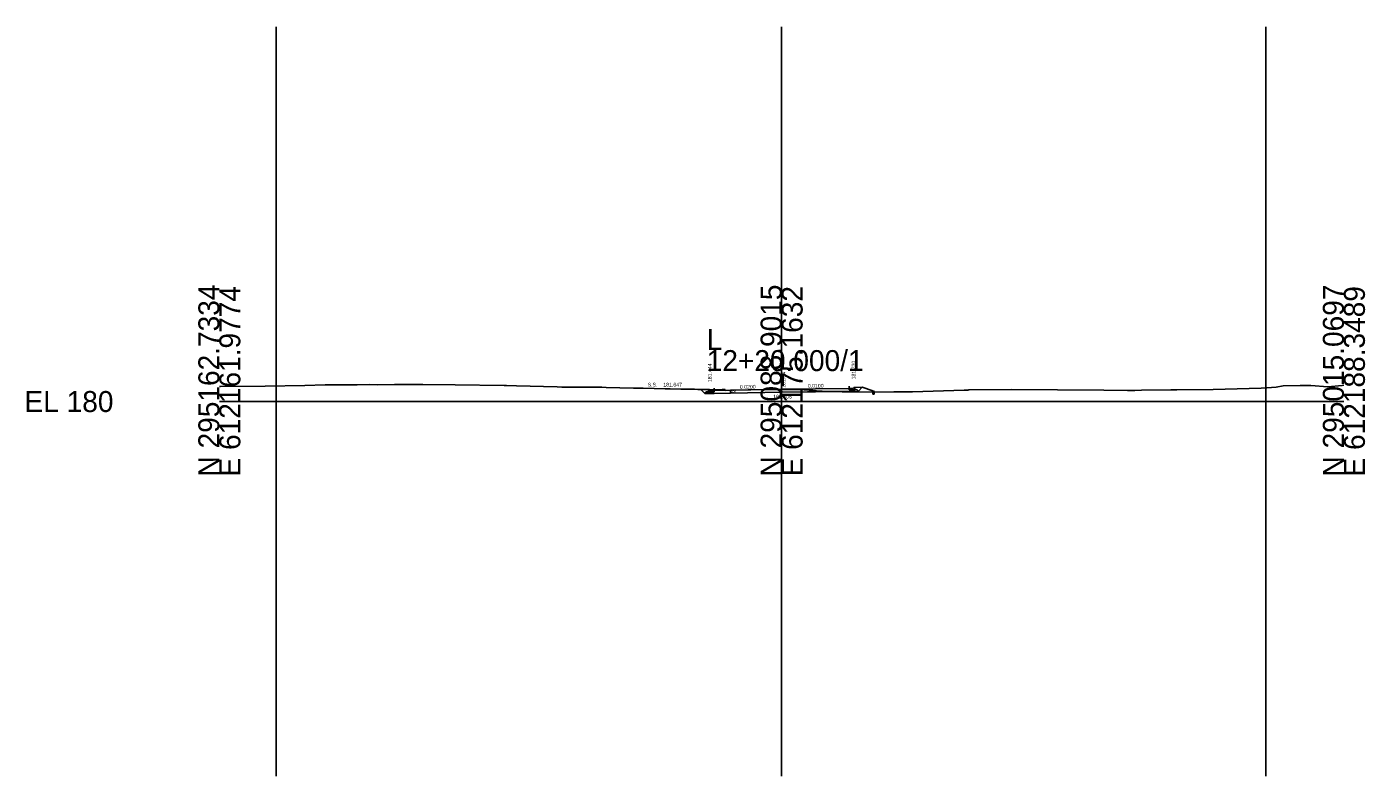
# Model space of a CAD drawing. Extents: x -81 to 616364, y 450 to 299952.
# Drawn here: x 535426.7 to 535605.2, y 120298.4 to 120398.4 of the extents above; entities that cross this region are included whole.
import ezdxf

# ---------------------------------------------------------------- set-up
doc = ezdxf.new("R2010")
doc.units = 0
for name, color, linetype in [('Exist XS Ground Line', 7, 'Continuous'), ('Old_Level_10', 7, 'Continuous'), ('Old_Level_17', 7, 'Continuous'), ('Old_Level_63', 7, 'Continuous'), ('Prop XS Dump Level', 7, 'Continuous'), ('Prop XS Earthwork Shape', 7, 'Continuous'), ('Prop XS EOT Tick Mark', 7, 'Continuous'), ('Prop XS Exc Vertical Line 1', 7, 'Continuous'), ('Prop XS Exc Vertical Line 2', 7, 'Continuous'), ('Prop XS Exc Vertical Line 3', 7, 'Continuous'), ('Prop XS Finish Grade', 7, 'Continuous'), ('Prop XS Finish Grade Concrete', 7, 'Continuous'), ('Prop XS Finish Grade Earthwork', 7, 'Continuous'), ('Prop XS Finish Grade Pavement', 7, 'Continuous'), ('Prop XS Pvmt Edge Slope', 7, 'Continuous'), ('Prop XS Side Slope Text', 7, 'Continuous'), ('Prop XS Subgrade Concrete', 7, 'Continuous'), ('Prop XS Subgrade Earthwork', 7, 'Continuous')]:
    doc.layers.add(name, color=color, linetype=linetype)

msp = doc.modelspace()

# ---------------------------------------------------------------- linework, layer by layer
at = {"layer": 'Exist XS Ground Line'}
for points in [[(535452.36, 120350.35), (535452.5, 120350.35), (535458.46, 120350.43), (535463.78, 120350.49), (535466.46, 120350.59), (535470.75, 120350.59), (535472.36, 120350.62), (535473.43, 120350.61), (535475.73, 120350.63), (535478.17, 120350.65), (535479.51, 120350.64), (535483.82, 120350.61), (535490.36, 120350.48), (535490.68, 120350.48), (535492.01, 120350.45), (535497.41, 120350.3), (535498.04, 120350.29), (535503.24, 120350.26), (535503.36, 120350.26), (535503.97, 120350.25), (535507.62, 120350.16), (535508.87, 120350.15), (535511.83, 120350.07), (535512.49, 120350.05), (535513.91, 120350.02), (535515.76, 120350), (535517.97, 120349.9), (535519.43, 120349.98), (535519.57, 120349.98), (535519.79, 120349.98), (535519.94, 120349.83), (535520.55, 120349.88), (535520.8, 120349.88), (535525.68, 120349.96), (535527.36, 120349.97), (535527.5, 120349.97), (535527.64, 120349.96), (535530.38, 120349.91), (535530.56, 120349.9), (535532.5, 120349.76), (535532.75, 120349.75), (535534.37, 120349.69), (535535.43, 120349.67), (535539.6, 120349.63), (535542.32, 120349.64), (535544.83, 120349.64), (535551.73, 120349.88), (535552.18, 120349.89), (535552.34, 120349.9), (535557.99, 120349.97), (535570.32, 120349.87), (535573.49, 120349.84), (535574.47, 120349.85), (535575.38, 120349.87), (535579.27, 120349.9), (535580.07, 120349.92), (535584.92, 120349.97), (535591.33, 120350.14), (535592.07, 120350.18), (535593.32, 120350.27), (535594.26, 120350.45), (535596.53, 120350.5), (535597.45, 120350.52), (535597.93, 120350.48), (535600.22, 120350.32)], [(535600.22, 120350.32), (535602.15, 120350.51), (535602.36, 120350.54)]]:
    msp.add_lwpolyline(points, dxfattribs=at)
at = {"layer": 'Old_Level_10'}
msp.add_line((535539.51, 120349.63), (535539.51, 120349.78), dxfattribs=at)
at = {"layer": 'Old_Level_17'}
for p, q in [((535539.51, 120349.77), (535539.52, 120349.78)), ((535539.54, 120349.76), (535539.51, 120349.76)), ((535539.51, 120349.63), (535539.71, 120349.63)), ((535539.51, 120349.33), (535539.51, 120349.63)), ((535539.51, 120349.57), (535539.54, 120349.59)), ((535539.54, 120349.59), (535539.51, 120349.59)), ((535539.51, 120349.48), (535539.53, 120349.5)), ((535539.54, 120349.47), (535539.51, 120349.47)), ((535539.71, 120349.33), (535539.51, 120349.33)), ((535539.52, 120349.78), (535539.57, 120349.78)), ((535539.53, 120349.78), (535539.54, 120349.76)), ((535539.53, 120349.5), (535539.54, 120349.47)), ((535539.6, 120349.77), (535539.71, 120349.66)), ((535539.6, 120349.77), (535539.6, 120349.77)), ((535539.62, 120349.68), (535539.61, 120349.66)), ((535539.61, 120349.66), (535539.65, 120349.67)), ((535539.62, 120349.39), (535539.61, 120349.37)), ((535539.61, 120349.37), (535539.65, 120349.38)), ((535539.65, 120349.67), (535539.62, 120349.68)), ((535539.65, 120349.38), (535539.62, 120349.39)), ((535539.69, 120349.46), (535539.71, 120349.49)), ((535539.71, 120349.46), (535539.69, 120349.46)), ((535539.7, 120349.58), (535539.71, 120349.55)), ((535539.71, 120349.57), (535539.7, 120349.58)), ((535539.71, 120349.66), (535539.71, 120349.33)), ((535539.71, 120349.55), (535539.71, 120349.56)), ((535539.71, 120349.49), (535539.71, 120349.48))]:
    msp.add_line(p, q, dxfattribs=at)
for centre in [(535539.53, 120349.55), (535539.54, 120349.72), (535539.54, 120349.68), (535539.54, 120349.43), (535539.54, 120349.39), (535539.56, 120349.53), (535539.57, 120349.62), (535539.57, 120349.51), (535539.59, 120349.57), (535539.59, 120349.72), (535539.59, 120349.66), (535539.59, 120349.43), (535539.59, 120349.37), (535539.62, 120349.74), (535539.61, 120349.53), (535539.61, 120349.49), (535539.62, 120349.45), (535539.62, 120349.62), (535539.62, 120349.58), (535539.62, 120349.54), (535539.63, 120349.71), (535539.63, 120349.42), (535539.64, 120349.49), (535539.66, 120349.64), (535539.66, 120349.34), (535539.67, 120349.68), (535539.67, 120349.59), (535539.67, 120349.44), (535539.67, 120349.39), (535539.68, 120349.53), (535539.69, 120349.64), (535539.69, 120349.35), (535539.71, 120349.52)]:
    msp.add_circle(centre, 0.00196, dxfattribs=at)
for centre, radius, start, end in [((535539.52, 120349.78), 0.006, 90, 180), ((535539.51, 120349.73), 0.00196, 325.5013, 34.4987), ((535539.52, 120349.52), 0.00196, 197.8106, 162.1894), ((535539.57, 120349.73), 0.05, 45, 90), ((535539.57, 120349.33), 0.00196, 342.3416, 197.6584), ((535539.62, 120349.33), 0.00196, 24.915, 155.085), ((535539.71, 120349.43), 0.00196, 76.8767, 283.1233)]:
    msp.add_arc(centre, radius, start, end, dxfattribs=at)
at = {"layer": 'Old_Level_63'}
for p, q in [((535527.36, 120348.36), (535527.36, 120355.22)), ((535452.36, 120348.36), (535527.36, 120348.36)), ((535527.36, 120348.36), (535602.36, 120348.36))]:
    msp.add_line(p, q, dxfattribs=at)
at = {"layer": 'Prop XS Dump Level'}
for p, q in [((535518.36, 120349.83), (535527.37, 120350.01)), ((535527.37, 120350.01), (535536.36, 120350.1))]:
    msp.add_line(p, q, dxfattribs=at)
at = {"layer": 'Prop XS Earthwork Shape'}
for points in [[(535515.76, 120350), (535516.18, 120349.98), (535514.83, 120350.01)], [(535516.18, 120349.98), (535514.83, 120350.01), (535515.76, 120350)], [(535516.18, 120349.98), (535514.83, 120350.01), (535515.76, 120350)], [(535515.76, 120350), (535516.18, 120349.98), (535514.83, 120350.01)], [(535515.76, 120350), (535516.18, 120349.98), (535514.83, 120350.01)], [(535516.18, 120349.98), (535514.83, 120350.01), (535515.76, 120350)], [(535516.59, 120349.98), (535516.18, 120349.98), (535516.6, 120349.96)], [(535516.59, 120349.98), (535516.18, 120349.98), (535516.6, 120349.96)], [(535516.59, 120349.98), (535516.18, 120349.98), (535516.6, 120349.96)], [(535516.59, 120349.98), (535516.18, 120349.98), (535516.6, 120349.96)], [(535516.59, 120349.98), (535516.18, 120349.98), (535516.6, 120349.96)], [(535516.59, 120349.98), (535516.6, 120349.96), (535516.18, 120349.98)], [(535516.6, 120349.96), (535517.97, 120349.9), (535519.43, 120349.98), (535519.57, 120349.98), (535519.79, 120349.98), (535519.94, 120349.83), (535520.55, 120349.88), (535520.55, 120349.49), (535518.36, 120349.45), (535517.11, 120349.45)], [(535517.11, 120349.45), (535518.36, 120349.45), (535520.55, 120349.49), (535520.55, 120349.88), (535519.94, 120349.83), (535519.79, 120349.98), (535519.57, 120349.98), (535519.43, 120349.98), (535517.97, 120349.9), (535516.6, 120349.96)], [(535517.11, 120349.45), (535518.36, 120349.45), (535520.55, 120349.49), (535520.55, 120349.88), (535519.94, 120349.83), (535519.79, 120349.98), (535519.57, 120349.98), (535519.43, 120349.98), (535517.97, 120349.9), (535516.6, 120349.96)], [(535517.11, 120349.45), (535518.36, 120349.45), (535520.55, 120349.49), (535520.55, 120349.88), (535519.94, 120349.83), (535519.79, 120349.98), (535519.57, 120349.98), (535519.43, 120349.98), (535517.97, 120349.9), (535516.6, 120349.96)], [(535517.11, 120349.45), (535518.36, 120349.45), (535520.55, 120349.49), (535520.55, 120349.88), (535519.94, 120349.83), (535519.79, 120349.98), (535519.57, 120349.98), (535519.43, 120349.98), (535517.97, 120349.9), (535516.6, 120349.96)], [(535518.36, 120349.45), (535520.55, 120349.49), (535520.55, 120349.88), (535519.94, 120349.83), (535519.79, 120349.98), (535519.57, 120349.98), (535519.43, 120349.98), (535517.97, 120349.9), (535516.6, 120349.96), (535517.11, 120349.45)], [(535520.55, 120349.49), (535527.37, 120349.63), (535534.25, 120349.7), (535532.75, 120349.75), (535532.5, 120349.76), (535530.56, 120349.9), (535530.38, 120349.91), (535527.64, 120349.96), (535527.5, 120349.97), (535527.36, 120349.97), (535525.68, 120349.96), (535520.8, 120349.88), (535520.56, 120349.88)], [(535520.55, 120349.49), (535527.37, 120349.63), (535534.25, 120349.7), (535532.75, 120349.75), (535532.5, 120349.76), (535530.56, 120349.9), (535530.38, 120349.91), (535527.64, 120349.96), (535527.5, 120349.97), (535527.36, 120349.97), (535525.68, 120349.96), (535520.8, 120349.88), (535520.56, 120349.88)], [(535520.55, 120349.49), (535527.37, 120349.63), (535534.25, 120349.7), (535532.75, 120349.75), (535532.5, 120349.76), (535530.56, 120349.9), (535530.38, 120349.91), (535527.64, 120349.96), (535527.5, 120349.97), (535527.36, 120349.97), (535525.68, 120349.96), (535520.8, 120349.88), (535520.56, 120349.88)], [(535520.55, 120349.49), (535527.37, 120349.63), (535534.25, 120349.7), (535532.75, 120349.75), (535532.5, 120349.76), (535530.56, 120349.9), (535530.38, 120349.91), (535527.64, 120349.96), (535527.5, 120349.97), (535527.36, 120349.97), (535525.68, 120349.96), (535520.8, 120349.88), (535520.56, 120349.88)], [(535520.55, 120349.49), (535527.37, 120349.63), (535534.25, 120349.7), (535532.75, 120349.75), (535532.5, 120349.76), (535530.56, 120349.9), (535530.38, 120349.91), (535527.64, 120349.96), (535527.5, 120349.97), (535527.36, 120349.97), (535525.68, 120349.96), (535520.8, 120349.88), (535520.56, 120349.88)], [(535525.68, 120349.96), (535527.36, 120349.97), (535527.37, 120349.63), (535520.55, 120349.49), (535520.56, 120349.88), (535520.8, 120349.88)], [(535527.37, 120349.63), (535534.25, 120349.7), (535532.75, 120349.75), (535532.5, 120349.76), (535530.56, 120349.9), (535530.38, 120349.91), (535527.64, 120349.96), (535527.5, 120349.97), (535527.36, 120349.97)], [(535535.43, 120349.67), (535539.51, 120349.63), (535539.51, 120349.78), (535538.12, 120350.26), (535537.61, 120349.76), (535536.36, 120349.72), (535534.25, 120349.7), (535534.37, 120349.69)], [(535539.51, 120349.78), (535539.51, 120349.63), (535535.43, 120349.67), (535534.37, 120349.69), (535534.25, 120349.7), (535536.36, 120349.72), (535537.61, 120349.76), (535538.12, 120350.26)], [(535539.51, 120349.78), (535539.51, 120349.63), (535535.43, 120349.67), (535534.37, 120349.69), (535534.25, 120349.7), (535536.36, 120349.72), (535537.61, 120349.76), (535538.12, 120350.26)], [(535539.51, 120349.78), (535539.51, 120349.63), (535535.43, 120349.67), (535534.37, 120349.69), (535534.25, 120349.7), (535536.36, 120349.72), (535537.61, 120349.76), (535538.12, 120350.26)], [(535539.51, 120349.78), (535539.51, 120349.63), (535535.43, 120349.67), (535534.37, 120349.69), (535534.25, 120349.7), (535536.36, 120349.72), (535537.61, 120349.76), (535538.12, 120350.26)], [(535537.61, 120349.76), (535538.12, 120350.26), (535539.51, 120349.78), (535539.51, 120349.63), (535535.43, 120349.67), (535534.37, 120349.69), (535534.25, 120349.7), (535536.36, 120349.72)]]:
    msp.add_lwpolyline(points, close=True, dxfattribs=at)
at = {"layer": 'Prop XS EOT Tick Mark'}
for p, q in [((535518.36, 120350.13), (535518.36, 120349.83)), ((535536.36, 120350.1), (535536.36, 120350.4))]:
    msp.add_line(p, q, dxfattribs=at)
at = {"layer": 'Prop XS Exc Vertical Line 1'}
msp.add_line((535459.94, 120398.36), (535459.94, 120298.36), dxfattribs=at)
at = {"layer": 'Prop XS Exc Vertical Line 2'}
msp.add_line((535527.36, 120398.36), (535527.36, 120298.36), dxfattribs=at)
at = {"layer": 'Prop XS Exc Vertical Line 3'}
msp.add_line((535591.96, 120398.36), (535591.96, 120298.36), dxfattribs=at)
at = {"layer": 'Prop XS Finish Grade'}
for p, q in [((535516.59, 120349.98), (535517.61, 120349.96)), ((535537.11, 120350.24), (535538.12, 120350.26))]:
    msp.add_line(p, q, dxfattribs=at)
at = {"layer": 'Prop XS Finish Grade Concrete'}
for p, q in [((535517.69, 120349.96), (535517.61, 120349.96)), ((535517.73, 120349.95), (535517.69, 120349.96)), ((535517.73, 120349.95), (535517.75, 120349.92)), ((535536.36, 120350.1), (535536.89, 120350.09)), ((535536.89, 120350.09), (535536.93, 120350.1)), ((535536.93, 120350.1), (535536.95, 120350.13)), ((535536.95, 120350.13), (535536.97, 120350.21)), ((535536.97, 120350.21), (535537, 120350.23)), ((535537.04, 120350.24), (535537, 120350.23)), ((535537.11, 120350.24), (535537.04, 120350.24)), ((535517.75, 120349.92), (535517.78, 120349.84)), ((535517.78, 120349.84), (535517.8, 120349.82)), ((535517.8, 120349.82), (535517.84, 120349.81)), ((535517.84, 120349.81), (535518.36, 120349.83))]:
    msp.add_line(p, q, dxfattribs=at)
at = {"layer": 'Prop XS Finish Grade Earthwork'}
for p, q in [((535516.59, 120349.98), (535514.76, 120350.01)), ((535514.76, 120350.01), (535514.76, 120350.01)), ((535538.12, 120350.26), (535539.51, 120349.78)), ((535539.51, 120349.78), (535539.51, 120349.63))]:
    msp.add_line(p, q, dxfattribs=at)
at = {"layer": 'Prop XS Finish Grade Pavement'}
for p, q in [((535527.37, 120350.01), (535518.36, 120349.83)), ((535536.36, 120350.1), (535527.37, 120350.01))]:
    msp.add_line(p, q, dxfattribs=at)
at = {"layer": 'Prop XS Pvmt Edge Slope'}
for p, q in [((535537.11, 120349.94), (535537.41, 120349.95)), ((535537.41, 120349.95), (535537.61, 120349.76)), ((535517.11, 120349.45), (535517.31, 120349.65)), ((535517.31, 120349.65), (535517.61, 120349.65))]:
    msp.add_line(p, q, dxfattribs=at)
at = {"layer": 'Prop XS Subgrade Concrete'}
for p, q in [((535517.61, 120349.96), (535517.61, 120349.65)), ((535536.36, 120350.1), (535536.36, 120349.92)), ((535536.36, 120349.92), (535537.11, 120349.94)), ((535537.11, 120349.94), (535537.11, 120350.24)), ((535517.61, 120349.65), (535518.36, 120349.65)), ((535518.36, 120349.65), (535518.36, 120349.83))]:
    msp.add_line(p, q, dxfattribs=at)
at = {"layer": 'Prop XS Subgrade Earthwork'}
for p, q in [((535516.59, 120349.98), (535517.11, 120349.45)), ((535537.61, 120349.76), (535538.12, 120350.26)), ((535517.11, 120349.45), (535518.36, 120349.45)), ((535518.36, 120349.45), (535520.55, 120349.49)), ((535520.56, 120349.88), (535520.55, 120349.49)), ((535520.55, 120349.49), (535520.55, 120349.88)), ((535520.55, 120349.49), (535527.37, 120349.63)), ((535527.37, 120349.63), (535536.36, 120349.72)), ((535536.36, 120349.72), (535537.61, 120349.76))]:
    msp.add_line(p, q, dxfattribs=at)

# ---------------------------------------------------------------- texts
at = {"layer": 'Old_Level_63'}
for s, p in [('N 295162.7334', (535452.36, 120338.36)), ('E 612161.9774', (535455.16, 120338.36)), ('N 295088.9015', (535527.36, 120338.36)), ('E 612175.1632', (535530.16, 120338.37)), ('N 295015.0697', (535602.36, 120338.36)), ('E 612188.3489', (535605.16, 120338.36))]:
    msp.add_text(s, height=2.8, rotation=90, dxfattribs=at).set_placement(p)
for s, p in [('L', (535517.36, 120355.22)), ('12+20.000/1', (535517.37, 120352.42)), ('EL 180', (535426.37, 120346.96))]:
    msp.add_text(s, height=2.8, dxfattribs=at).set_placement(p)
at = {"layer": 'Prop XS Dump Level'}
msp.add_text('Eop', height=0.3, dxfattribs=at).set_placement((535520.55, 120349.58))
at = {"layer": 'Prop XS Side Slope Text'}
for s, rotation, p in [('181.730', 90, (535537.21, 120351.31)), ('181.444', 90, (535518.03, 120350.95)), (' 181.64', 90, (535527.86, 120350.01)), ('0.0200', 1.1457, (535521.79, 120350.05)), ('0.0100', 0.5729, (535530.85, 120350.2))]:
    msp.add_text(s, height=0.5, rotation=rotation, dxfattribs=at).set_placement(p)
for s, p in [('S.S.    181.647', (535509.5, 120350.36)), ('181.606', (535526.22, 120348.76))]:
    msp.add_text(s, height=0.5, dxfattribs=at).set_placement(p)

doc.saveas('drawing.dxf')
